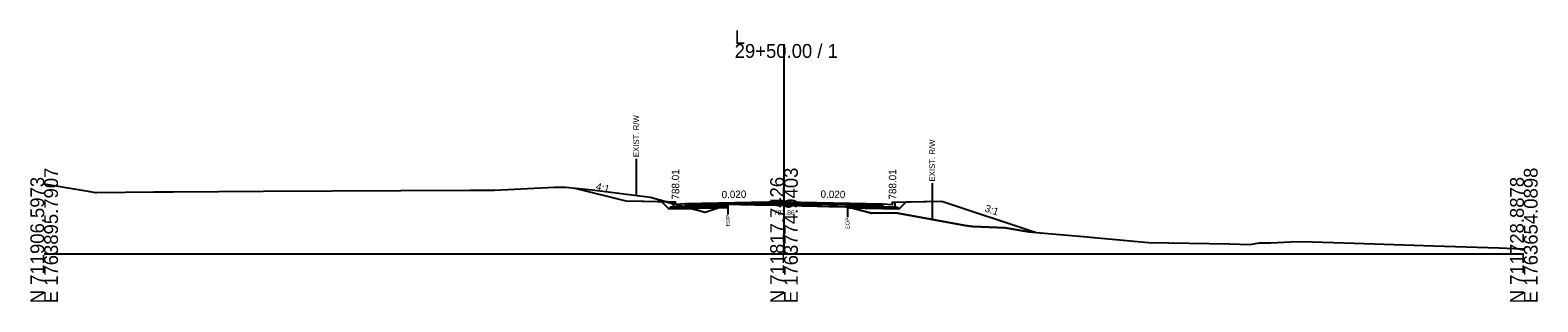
# Model space of a CAD drawing. Extents: x -26 to 5303, y -10 to 9578.
# Drawn here: x 997.2 to 1302.8, y 9490.3 to 9545.3 of the extents above; entities that cross this region are included whole.
import ezdxf

# ---------------------------------------------------------------- set-up
doc = ezdxf.new("R2010")
doc.units = 0
for name, color, linetype in [('Default', 7, 'Continuous'), ('Exist CMT Pavement', 7, 'Continuous'), ('Exist Cross Section Cell', 7, 'Continuous'), ('Exist XS Ground Line', 7, 'Continuous'), ('Old_Level_10', 7, 'Continuous'), ('Old_Level_3', 7, 'Continuous'), ('Prop CMT Conc Surface', 7, 'Continuous'), ('Prop CMT Concrete Structures', 7, 'Continuous'), ('Prop CMT Pvmt Course 1', 7, 'Continuous'), ('Prop CMT Pvmt Course 1 CG', 7, 'Continuous'), ('Prop CMT Pvmt Course 2', 7, 'Continuous'), ('Prop CMT Pvmt Course 3', 7, 'Continuous'), ('Prop CMT Pvmt Surface', 7, 'Continuous'), ('Prop CMT Slope Grass', 7, 'Continuous'), ('Prop CMT Subgrade Earthwork', 7, 'Continuous'), ('Prop XS Earthwork Shape', 7, 'Continuous'), ('Prop XS Hydro Elevations', 7, 'Continuous'), ('Prop XS SE Text', 7, 'Continuous'), ('Prop XS Side Slope Text', 7, 'Continuous'), ('Prop XS Wedging', 7, 'Continuous')]:
    doc.layers.add(name, color=color, linetype=linetype)

msp = doc.modelspace()

# ---------------------------------------------------------------- linework, layer by layer
at = {"layer": 'Exist CMT Pavement'}
msp.add_lwpolyline([(1138.61, 9510.03), (1139.4, 9510.06), (1139.86, 9510.05), (1141.19, 9510.04), (1142.17, 9510.03), (1142.98, 9510.01), (1144.08, 9509.98), (1145.27, 9509.96), (1148.37, 9509.91), (1150.35, 9509.84), (1150.94, 9509.85), (1151.48, 9509.83), (1151.92, 9509.81), (1152.52, 9509.8), (1153.71, 9509.77), (1154.58, 9509.75), (1155.5, 9509.72), (1156.74, 9509.7), (1157.68, 9509.67), (1159.07, 9509.59), (1160.88, 9509.59), (1162.49, 9509.53), (1162.88, 9509.51)], dxfattribs=at)
at = {"layer": 'Exist Cross Section Cell'}
for p, q in [((1150, 9500), (1150, 9542.52)), ((1000, 9500), (1150, 9500)), ((1150, 9500), (1300, 9500))]:
    msp.add_line(p, q, dxfattribs=at)
at = {"layer": 'Exist XS Ground Line'}
msp.add_lwpolyline([(1000, 9514.17), (1008.95, 9512.74), (1010.32, 9512.47), (1010.68, 9512.46), (1022.24, 9512.61), (1022.79, 9512.61), (1026.24, 9512.61), (1044.39, 9512.7), (1086.28, 9512.9), (1087.86, 9512.9), (1091.28, 9512.9), (1103.43, 9513.52), (1105.67, 9513.5), (1111.11, 9513.01), (1122.92, 9511.53), (1127.32, 9510.24), (1133.99, 9508.43), (1138.61, 9510.03), (1139.4, 9510.06), (1139.86, 9510.05), (1142.17, 9510.03), (1144.08, 9509.98), (1144.77, 9509.96), (1145.27, 9509.96), (1146.55, 9509.94), (1148.37, 9509.91), (1150.13, 9509.85), (1150.94, 9509.85), (1151.48, 9509.83), (1151.92, 9509.81), (1152.52, 9509.8), (1153.71, 9509.77), (1154.58, 9509.75), (1155.5, 9509.72), (1156.74, 9509.7), (1157.28, 9509.68), (1157.68, 9509.67), (1159.07, 9509.59), (1160.88, 9509.59), (1162.49, 9509.53), (1162.88, 9509.51), (1167.79, 9508.28), (1172.67, 9508.31), (1186.74, 9505.75), (1187.67, 9505.63), (1188.28, 9505.56), (1194.83, 9505.32), (1199.64, 9504.51), (1205.89, 9503.92), (1210.69, 9503.54), (1215.08, 9503.13), (1223.91, 9502.33), (1240.33, 9502.07), (1244.44, 9501.93), (1246.43, 9502.28), (1248.73, 9502.28), (1252.67, 9502.48), (1255.07, 9502.49), (1267.71, 9502.11), (1281.65, 9501.67), (1294.98, 9501.26), (1298.03, 9501.12), (1300, 9501.05)], dxfattribs=at)
at = {"layer": 'Old_Level_10'}
for p, q in [((1120.03, 9519.29), (1120.03, 9511.89)), ((1180.03, 9514.37), (1180.03, 9506.97)), ((1138.61, 9510.03), (1138.61, 9507.98)), ((1162.88, 9509.51), (1162.88, 9507.46))]:
    msp.add_line(p, q, dxfattribs=at)
at = {"layer": 'Prop CMT Conc Surface'}
for points in [[(1128, 9510.01), (1128, 9510.51), (1127.5, 9510.51)], [(1130, 9510.13), (1128, 9510.01)], [(1170, 9510.13), (1172, 9510.01)], [(1172, 9510.01), (1172, 9510.51), (1172.5, 9510.51)]]:
    msp.add_lwpolyline(points, dxfattribs=at)
at = {"layer": 'Prop CMT Concrete Structures'}
for points in [[(1130, 9510.13), (1128, 9510.01), (1128, 9510.51), (1127.5, 9510.51)], [(1127.5, 9510.51), (1127.5, 9509.49), (1130, 9509.54)], [(1130, 9509.54), (1130, 9510.13)], [(1170, 9510.13), (1172, 9510.01), (1172, 9510.51), (1172.5, 9510.51)], [(1172.5, 9510.51), (1172.5, 9509.49), (1170, 9509.54)], [(1170, 9509.54), (1170, 9510.13)]]:
    msp.add_lwpolyline(points, dxfattribs=at)
at = {"layer": 'Prop CMT Pvmt Course 1'}
for points in [[(1150, 9510.53), (1130, 9510.13)], [(1130, 9510.13), (1130, 9509.88)], [(1130, 9509.88), (1138.61, 9510.05)], [(1138.61, 9510.05), (1150, 9510.28)], [(1138.61, 9510.05), (1138.61, 9510.05)], [(1150, 9510.28), (1150, 9510.53)], [(1150, 9510.53), (1170, 9510.13)], [(1150, 9510.28), (1150, 9510.28), (1150, 9510.28)], [(1162.88, 9510.02), (1150, 9510.28)], [(1170, 9509.88), (1162.88, 9510.02)], [(1162.88, 9510.02), (1162.88, 9510.02)], [(1170, 9510.13), (1170, 9509.88)]]:
    msp.add_lwpolyline(points, dxfattribs=at)
at = {"layer": 'Prop CMT Pvmt Course 1 CG'}
for points in [[(1130, 9509.54), (1127, 9509.48), (1126.66, 9509.14)], [(1126.66, 9509.14), (1130, 9509.21)], [(1130, 9509.21), (1130, 9509.54)], [(1170, 9509.54), (1173, 9509.48), (1173.34, 9509.14)], [(1170, 9509.21), (1170, 9509.54)], [(1173.34, 9509.14), (1170, 9509.21)]]:
    msp.add_lwpolyline(points, dxfattribs=at)
at = {"layer": 'Prop CMT Pvmt Course 2'}
for points in [[(1138.61, 9510.05), (1130, 9509.88)], [(1130, 9509.88), (1130, 9509.54)], [(1138.61, 9509.71), (1138.61, 9510.05)], [(1162.88, 9509.68), (1162.88, 9510.02)], [(1162.88, 9510.02), (1170, 9509.88)], [(1170, 9509.88), (1170, 9509.54)], [(1130, 9509.54), (1138.61, 9509.71)], [(1170, 9509.54), (1162.88, 9509.68)]]:
    msp.add_lwpolyline(points, dxfattribs=at)
at = {"layer": 'Prop CMT Pvmt Course 3'}
for points in [[(1138.61, 9509.71), (1130, 9509.54)], [(1130, 9509.54), (1130, 9509.21)], [(1130, 9509.21), (1138.61, 9509.38)], [(1138.61, 9509.38), (1138.61, 9509.71)], [(1162.88, 9509.68), (1170, 9509.54)], [(1162.88, 9509.35), (1162.88, 9509.68)], [(1170, 9509.21), (1162.88, 9509.35)], [(1170, 9509.54), (1170, 9509.21)]]:
    msp.add_lwpolyline(points, dxfattribs=at)
at = {"layer": 'Prop CMT Pvmt Surface'}
for points in [[(1150, 9510.53), (1130, 9510.13)], [(1150, 9510.53), (1170, 9510.13)]]:
    msp.add_lwpolyline(points, dxfattribs=at)
at = {"layer": 'Prop CMT Slope Grass'}
for points in [[(1127.5, 9510.51), (1118, 9510.7), (1107.41, 9513.34)], [(1172.5, 9510.51), (1182, 9510.7), (1200.94, 9504.38)]]:
    msp.add_lwpolyline(points, dxfattribs=at)
at = {"layer": 'Prop CMT Subgrade Earthwork'}
for p, q in [((1138.61, 9510.03), (1138.61, 9509.38)), ((1162.88, 9509.51), (1162.88, 9509.35))]:
    msp.add_line(p, q, dxfattribs=at)
for points in [[(1130, 9509.21), (1126.66, 9509.14), (1125.25, 9510.55)], [(1170, 9509.21), (1173.34, 9509.14), (1174.75, 9510.55)], [(1138.61, 9509.38), (1130, 9509.21)], [(1162.88, 9509.35), (1170, 9509.21)]]:
    msp.add_lwpolyline(points, dxfattribs=at)
at = {"layer": 'Prop XS Earthwork Shape'}
for points in [[(1126.32, 9510.53), (1125.25, 9510.55), (1118, 9510.7), (1107.41, 9513.34), (1111.11, 9513.01), (1122.92, 9511.53)], [(1126.32, 9510.53), (1125.25, 9510.55), (1126.66, 9509.14), (1130, 9509.21), (1131.04, 9509.23), (1128.14, 9510.01), (1128, 9510.01), (1128, 9510.05), (1127.32, 9510.24)], [(1128, 9510.01), (1128, 9510.05), (1128.14, 9510.01)], [(1138.61, 9510.03), (1138.61, 9509.38), (1136.63, 9509.34)], [(1174.75, 9510.55), (1182, 9510.7), (1200.94, 9504.38), (1199.64, 9504.51), (1194.83, 9505.32), (1188.28, 9505.56), (1187.67, 9505.63), (1186.74, 9505.75), (1172.67, 9508.31), (1167.79, 9508.28), (1163.59, 9509.34), (1170, 9509.21), (1173.34, 9509.14)], [(1136.63, 9509.34), (1131.04, 9509.23), (1133.99, 9508.43)], [(1162.88, 9509.35), (1163.59, 9509.34), (1162.88, 9509.51)]]:
    msp.add_lwpolyline(points, close=True, dxfattribs=at)
at = {"layer": 'Prop XS Wedging'}
for points in [[(1138.61, 9510.03), (1138.61, 9510.05), (1139.4, 9510.06), (1139.86, 9510.07), (1141.19, 9510.1), (1142.17, 9510.12), (1142.98, 9510.13), (1144.08, 9510.16), (1145.27, 9510.18), (1148.37, 9510.24), (1150, 9510.27), (1150.35, 9510.27), (1150.94, 9510.26), (1151.48, 9510.25), (1151.92, 9510.24), (1152.52, 9510.22), (1153.71, 9510.2), (1154.58, 9510.18), (1155.5, 9510.17), (1156.74, 9510.14), (1157.68, 9510.12), (1159.07, 9510.09), (1160.88, 9510.06), (1162.49, 9510.03), (1162.88, 9510.02), (1162.88, 9509.51), (1162.49, 9509.53), (1160.88, 9509.59), (1159.07, 9509.59), (1157.68, 9509.67), (1156.74, 9509.69), (1155.5, 9509.72), (1154.58, 9509.75), (1153.71, 9509.77), (1152.52, 9509.8), (1151.92, 9509.81), (1151.48, 9509.83), (1150.94, 9509.85), (1150.35, 9509.84), (1150, 9509.85), (1148.37, 9509.91), (1145.27, 9509.96), (1144.08, 9509.98), (1142.98, 9510.01), (1142.17, 9510.03), (1141.19, 9510.04), (1139.86, 9510.06), (1139.4, 9510.06)], [(1144.71, 9509.97), (1144.91, 9510.17), (1145.27, 9510.18), (1148.37, 9510.24), (1150, 9510.27), (1150.35, 9510.27), (1150.94, 9510.26), (1151.48, 9510.25), (1151.92, 9510.24), (1152.52, 9510.22), (1153.71, 9510.2), (1154.58, 9510.18), (1155.5, 9510.17), (1156.74, 9510.14), (1157.68, 9510.12), (1159.07, 9510.09), (1160.88, 9510.06), (1162.49, 9510.03), (1162.88, 9510.02), (1162.88, 9509.51), (1162.49, 9509.53), (1160.88, 9509.59), (1159.07, 9509.59), (1157.68, 9509.67), (1156.74, 9509.69), (1155.5, 9509.72), (1154.58, 9509.75), (1153.71, 9509.77), (1152.52, 9509.8), (1151.92, 9509.81), (1151.48, 9509.83), (1150.94, 9509.85), (1150.35, 9509.84), (1150, 9509.85), (1148.37, 9509.91), (1145.27, 9509.96)]]:
    msp.add_lwpolyline(points, close=True, dxfattribs=at)

# ---------------------------------------------------------------- texts
at = {"layer": 'Default'}
msp.add_text('-', height=0.0001, dxfattribs=at).set_placement((1000, 9500))
at = {"layer": 'Exist Cross Section Cell'}
for s, p in [('L', (1140, 9542.52)), ('29+50.00 / 1', (1140, 9539.72))]:
    msp.add_text(s, height=2.8, dxfattribs=at).set_placement(p)
for s, p in [('E 1763895.7907', (1002.8, 9490)), ('E 1763774.9403', (1152.8, 9490)), ('E 1763654.0898', (1302.8, 9490)), ('N 711906.5973', (1000, 9490)), ('N 711817.7426', (1150, 9490)), ('N 711728.8878', (1300, 9490))]:
    msp.add_text(s, height=2.8, rotation=90, dxfattribs=at).set_placement(p)
at = {"layer": 'Old_Level_10'}
for s, height, p in [('EXIST. R/W', 1.181, (1120.62, 9519.6)), ('EXIST. R/W', 1.181, (1180.62, 9514.67)), ('EOP', 0.787, (1139.01, 9505.58)), ('EOP', 0.787, (1163.28, 9505.07))]:
    msp.add_text(s, height=height, rotation=90, dxfattribs=at).set_placement(p)
at = {"layer": 'Old_Level_3'}
msp.add_text('787.86', height=1, dxfattribs=at).set_placement((1147.95, 9507.86))
at = {"layer": 'Prop XS Hydro Elevations'}
for p in [(1128.75, 9511.01), (1172.75, 9511.01)]:
    msp.add_text('788.01', height=1.5, rotation=90, dxfattribs=at).set_placement(p)
at = {"layer": 'Prop XS SE Text'}
for rotation, p in [(1.1458, (1137.36, 9511.27)), (358.8542, (1157.4, 9511.38))]:
    msp.add_text('0.020', height=1.5, rotation=rotation, dxfattribs=at).set_placement(p)
at = {"layer": 'Prop XS Side Slope Text'}
for s, rotation, p in [('4:1', 345.9638, (1111.73, 9513.04)), ('3:1', 341.5651, (1190.58, 9508.63))]:
    msp.add_text(s, height=1.5, rotation=rotation, dxfattribs=at).set_placement(p)

doc.saveas('drawing.dxf')
